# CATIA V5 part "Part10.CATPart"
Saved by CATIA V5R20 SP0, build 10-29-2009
Part number: FV161320-5
Revision: ANY
Definition: UNKNOWN
Nomenclature: FV161320-5
Source: Unknown
Bounding box of the stored display mesh (mm): x -5.476 to 5.476, y 0 to 6.05, z -5 to 5
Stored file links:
  C:\Users\Utente\Desktop\IO LAVORO\3D X SITO CF\CUMSA\3D files FV\FV 201720\Part10.CATPart
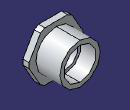
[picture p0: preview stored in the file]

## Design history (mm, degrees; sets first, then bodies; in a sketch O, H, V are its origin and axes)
Body1 "Cortar-Extruir2" (main body)
  Solid1: solid without history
